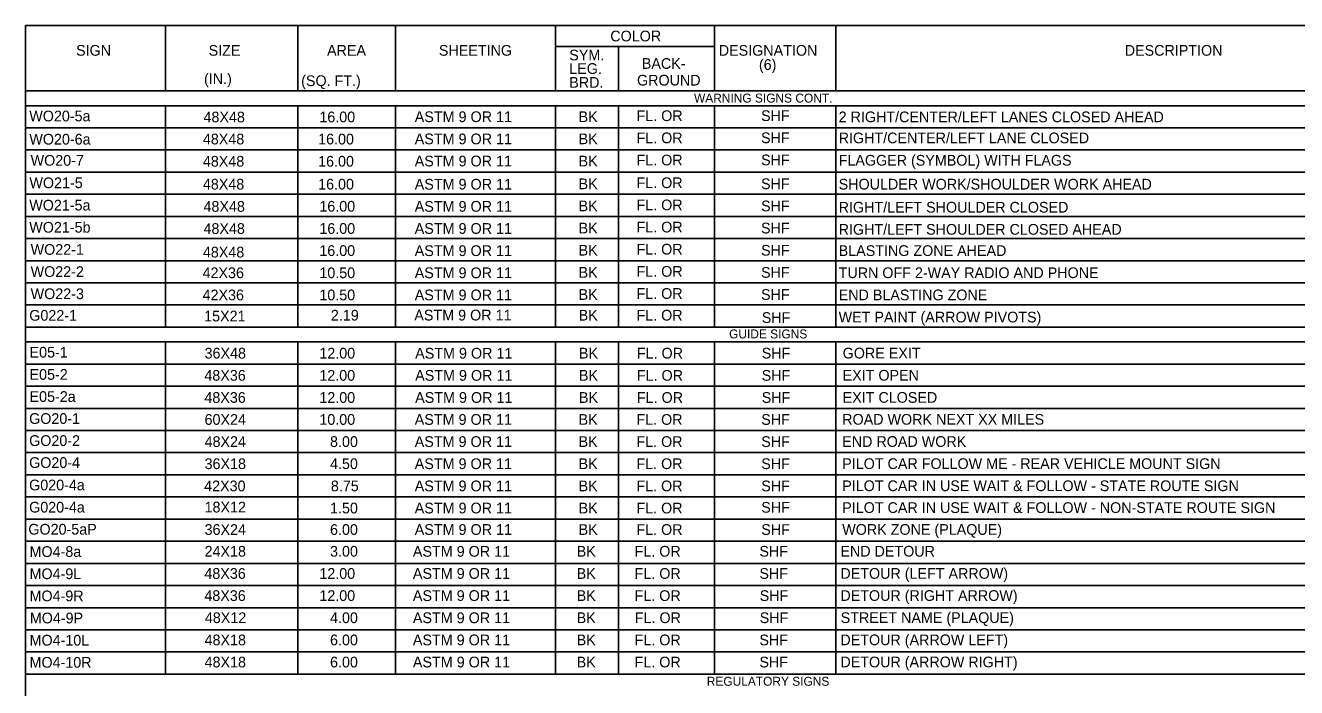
# Model space of a CAD drawing. Extents: x -439.1 to -407.9, y -458.1 to -437.7.
# Drawn here: x -439.11 to -421.29, y -446.95 to -437.68 of the extents above; entities that cross this region are included whole.
import ezdxf

# ---------------------------------------------------------------- set-up
doc = ezdxf.new("R2010")
doc.units = 0
for name, color, linetype in [('Common-Notes', 7, 'Continuous'), ('Level 4', 7, 'Continuous'), ('Level 45', 7, 'Continuous')]:
    doc.layers.add(name, color=color, linetype=linetype)

msp = doc.modelspace()

# ---------------------------------------------------------------- linework, layer by layer
at = {"layer": 'Common-Notes'}
msp.add_line((-439.109, -445.834), (-418.049, -445.834), dxfattribs=at)
at = {"layer": 'Level 4'}
for p, q in [((-439.109, -437.676), (-418.049, -437.676)), ((-439.109, -437.676), (-439.109, -457.952)), ((-437.145, -437.676), (-437.145, -438.59)), ((-435.291, -437.676), (-435.291, -438.59)), ((-433.919, -437.676), (-433.919, -438.59)), ((-431.677, -437.676), (-431.677, -438.59)), ((-429.447, -437.676), (-429.447, -438.59)), ((-427.749, -437.676), (-427.749, -438.59)), ((-431.677, -437.972), (-429.447, -437.972)), ((-430.792, -437.972), (-430.792, -438.59)), ((-439.109, -438.59), (-418.049, -438.59)), ((-439.109, -438.8), (-418.049, -438.8)), ((-437.145, -438.8), (-437.145, -441.903)), ((-435.291, -438.8), (-435.291, -441.903)), ((-433.919, -438.8), (-433.919, -441.903)), ((-431.677, -438.8), (-431.677, -441.903)), ((-430.792, -438.8), (-430.792, -441.903)), ((-429.447, -438.8), (-429.447, -441.903)), ((-427.749, -438.8), (-427.749, -441.903)), ((-439.109, -439.11), (-418.049, -439.11)), ((-439.109, -439.421), (-418.049, -439.421)), ((-439.109, -439.731), (-418.049, -439.731)), ((-439.109, -440.041), (-418.049, -440.041)), ((-439.109, -440.351), (-418.049, -440.351)), ((-439.109, -440.662), (-418.049, -440.662)), ((-439.109, -440.972), (-418.049, -440.972)), ((-439.109, -441.282), (-418.049, -441.282)), ((-439.109, -441.593), (-418.049, -441.593)), ((-439.109, -441.903), (-418.049, -441.903)), ((-439.109, -442.11), (-418.049, -442.11)), ((-437.145, -442.11), (-437.145, -446.765)), ((-435.291, -442.11), (-435.291, -446.455)), ((-433.919, -442.11), (-433.919, -446.765)), ((-431.677, -442.11), (-431.677, -446.455)), ((-430.792, -442.11), (-430.792, -446.455)), ((-429.916, -442.11), (-430.371, -442.11)), ((-429.447, -442.11), (-429.447, -446.765)), ((-427.749, -442.11), (-427.749, -446.765)), ((-439.109, -442.421), (-418.049, -442.421)), ((-439.109, -442.421), (-439.109, -442.731)), ((-439.109, -442.731), (-418.049, -442.731)), ((-439.109, -443.041), (-418.049, -443.041)), ((-439.109, -443.352), (-418.049, -443.352)), ((-439.109, -443.662), (-418.049, -443.662)), ((-439.109, -443.972), (-418.049, -443.972)), ((-439.109, -444.283), (-418.049, -444.283)), ((-439.109, -444.593), (-418.049, -444.593)), ((-439.109, -444.903), (-418.049, -444.903)), ((-439.109, -445.214), (-418.049, -445.214)), ((-439.109, -445.524), (-418.049, -445.524)), ((-439.109, -446.145), (-418.049, -446.145)), ((-439.109, -446.455), (-418.049, -446.455)), ((-435.291, -446.455), (-435.291, -446.765)), ((-431.677, -446.455), (-431.677, -446.765)), ((-430.792, -446.455), (-430.792, -446.765)), ((-418.049, -446.765), (-439.109, -446.765))]:
    msp.add_line(p, q, dxfattribs=at)

# ---------------------------------------------------------------- texts
for s, height, p in [('COLOR', 0.15, (-430.909, -437.899)), ('SIGN', 0.15, (-438.399, -438.1)), ('SIZE', 0.15, (-436.54, -438.1)), ('AREA', 0.15, (-434.88, -438.1)), ('SHEETING', 0.15, (-433.312, -438.1)), ('SYM.', 0.15, (-431.484, -438.165)), ('DESIGNATION', 0.15, (-429.388, -438.1)), ('DESCRIPTION', 0.15, (-423.696, -438.1)), ('LEG.', 0.15, (-431.484, -438.355)), ('BACK-', 0.15, (-430.467, -438.284)), ('(6)', 0.15, (-428.825, -438.299)), ('BRD.', 0.15, (-431.484, -438.549)), ('GROUND', 0.15, (-430.534, -438.518)), ('WARNING SIGNS CONT.', 0.125, (-429.735, -438.756)), ('WO20-5a', 0.15, (-439.055, -439.02)), ('ASTM 9 OR 11', 0.15044, (-433.651, -439.03)), ('BK', 0.15, (-431.353, -439.03)), ('FL. OR', 0.15, (-430.541, -439.016)), ('SHF', 0.15, (-428.795, -439.015)), ('2 RIGHT/CENTER/LEFT LANES CLOSED AHEAD', 0.15, (-427.707, -439.032)), ('WO20-6a', 0.15, (-439.054, -439.345)), ('ASTM 9 OR 11', 0.15044, (-433.651, -439.341)), ('BK', 0.15, (-431.353, -439.34)), ('FL. OR', 0.15, (-430.541, -439.326)), ('SHF', 0.15, (-428.795, -439.325)), ('RIGHT/CENTER/LEFT LANE CLOSED ', 0.15, (-427.707, -439.327)), ('WO20-7', 0.15, (-439.036, -439.641)), ('FL. OR', 0.15, (-430.541, -439.637)), ('SHF', 0.15, (-428.795, -439.635)), ('FLAGGER (SYMBOL) WITH FLAGS', 0.15, (-427.707, -439.64)), ('ASTM 9 OR 11', 0.15044, (-433.651, -439.651)), ('BK', 0.15, (-431.353, -439.651)), ('WO21-5', 0.15, (-439.053, -439.956)), ('ASTM 9 OR 11', 0.15044, (-433.651, -439.976)), ('BK', 0.15, (-431.353, -439.97)), ('FL. OR', 0.15, (-430.541, -439.955)), ('SHF', 0.15, (-428.795, -439.97)), ('SHOULDER WORK/SHOULDER WORK AHEAD', 0.15, (-427.707, -439.975)), ('WO21-5a', 0.15, (-439.055, -440.269)), ('ASTM 9 OR 11', 0.15044, (-433.651, -440.286)), ('BK', 0.15, (-431.353, -440.28)), ('FL. OR', 0.15, (-430.541, -440.266)), ('SHF', 0.15, (-428.795, -440.28)), ('RIGHT/LEFT SHOULDER CLOSED', 0.15, (-427.707, -440.298)), ('WO21-5b', 0.15, (-439.055, -440.579)), ('ASTM 9 OR 11', 0.15044, (-433.651, -440.596)), ('BK', 0.15, (-431.353, -440.59)), ('FL. OR', 0.15, (-430.541, -440.576)), ('SHF', 0.15, (-428.795, -440.59)), ('RIGHT/LEFT SHOULDER CLOSED AHEAD', 0.15, (-427.707, -440.608)), ('WO22-1', 0.15, (-439.036, -440.89)), ('FL. OR', 0.15, (-430.541, -440.886)), ('ASTM 9 OR 11', 0.15044, (-433.651, -440.907)), ('BK', 0.15, (-431.353, -440.9)), ('SHF', 0.15, (-428.795, -440.901)), ('BLASTING ZONE AHEAD', 0.15, (-427.707, -440.906)), ('WO22-2', 0.15, (-439.036, -441.2)), ('ASTM 9 OR 11', 0.15044, (-433.651, -441.217)), ('BK', 0.15, (-431.353, -441.211)), ('FL. OR', 0.15, (-430.541, -441.197)), ('SHF', 0.15, (-428.795, -441.211)), ('TURN OFF 2-WAY RADIO AND PHONE', 0.15, (-427.707, -441.216)), ('WO22-3', 0.15, (-439.036, -441.511)), ('ASTM 9 OR 11', 0.15044, (-433.651, -441.527)), ('BK', 0.15, (-431.353, -441.521)), ('FL. OR', 0.15, (-430.541, -441.507)), ('SHF', 0.15, (-428.795, -441.521)), ('END BLASTING ZONE', 0.15, (-427.707, -441.527)), ('G022-1', 0.15, (-439.055, -441.813)), ('ASTM 9 OR 11', 0.15044, (-433.657, -441.81)), ('BK', 0.15, (-431.352, -441.811)), ('FL. OR', 0.15, (-430.541, -441.811)), ('SHF', 0.15, (-428.785, -441.844)), ('WET PAINT (ARROW PIVOTS)', 0.15, (-427.707, -441.837)), ('GUIDE SIGNS', 0.125, (-429.243, -442.061)), ('E05-1', 0.15, (-439.051, -442.33)), ('ASTM 9 OR 11', 0.15044, (-433.645, -442.344)), ('BK', 0.15, (-431.348, -442.343)), ('FL. OR', 0.15, (-430.536, -442.343)), ('SHF', 0.15, (-428.786, -442.343)), ('GORE EXIT', 0.15, (-427.651, -442.342)), ('E05-2', 0.15, (-439.051, -442.641)), ('ASTM 9 OR 11', 0.15044, (-433.645, -442.654)), ('BK', 0.15, (-431.348, -442.654)), ('FL. OR', 0.15, (-430.536, -442.654)), ('SHF', 0.15, (-428.786, -442.654)), ('EXIT OPEN', 0.15, (-427.651, -442.653)), ('E05-2a', 0.15, (-439.051, -442.951)), ('ASTM 9 OR 11', 0.15044, (-433.645, -442.964)), ('BK', 0.15, (-431.348, -442.964)), ('FL. OR', 0.15, (-430.536, -442.964)), ('SHF', 0.15, (-428.786, -442.964)), ('EXIT CLOSED', 0.15, (-427.651, -442.963)), ('GO20-1', 0.15, (-439.057, -443.259)), ('ASTM 9 OR 11', 0.15044, (-433.651, -443.272)), ('BK', 0.15, (-431.353, -443.272)), ('FL. OR', 0.15, (-430.542, -443.272)), ('SHF', 0.15, (-428.792, -443.272)), ('ROAD WORK NEXT XX MILES', 0.15, (-427.657, -443.27)), ('GO20-2', 0.15, (-439.057, -443.568)), ('ASTM 9 OR 11', 0.15044, (-433.651, -443.582)), ('BK', 0.15, (-431.353, -443.582)), ('FL. OR', 0.15, (-430.542, -443.582)), ('SHF', 0.15, (-428.792, -443.582)), ('END ROAD WORK', 0.15, (-427.657, -443.581)), ('GO20-4', 0.15, (-439.057, -443.876)), ('ASTM 9 OR 11', 0.15044, (-433.651, -443.892)), ('BK', 0.15, (-431.353, -443.892)), ('FL. OR', 0.15, (-430.542, -443.892)), ('SHF', 0.15, (-428.792, -443.892)), ('PILOT CAR FOLLOW ME - REAR VEHICLE MOUNT SIGN', 0.15, (-427.657, -443.891)), ('G020-4a', 0.15, (-439.057, -444.19)), ('ASTM 9 OR 11', 0.15044, (-433.651, -444.203)), ('BK', 0.15, (-431.353, -444.203)), ('FL. OR', 0.15, (-430.542, -444.203)), ('SHF', 0.15, (-428.792, -444.203)), ('PILOT CAR IN USE WAIT & FOLLOW - STATE ROUTE SIGN', 0.15, (-427.657, -444.201)), ('G020-4a', 0.15, (-439.057, -444.501)), ('ASTM 9 OR 11', 0.15044, (-433.651, -444.513)), ('BK', 0.15, (-431.353, -444.513)), ('FL. OR', 0.15, (-430.542, -444.513)), ('SHF', 0.15, (-428.792, -444.503)), ('PILOT CAR IN USE WAIT & FOLLOW - NON-STATE ROUTE SIGN', 0.15, (-427.657, -444.507)), ('GO20-5aP', 0.15, (-439.068, -444.81)), ('ASTM 9 OR 11', 0.15044, (-433.651, -444.814)), ('FL. OR', 0.15, (-430.542, -444.814)), ('SHF', 0.15, (-428.792, -444.814)), ('WORK ZONE (PLAQUE)', 0.15, (-427.657, -444.813)), ('BK', 0.15, (-431.353, -444.814)), ('MO4-8a', 0.15, (-439.051, -445.123)), ('ASTM 9 OR 11', 0.15044, (-433.677, -445.12)), ('BK', 0.15, (-431.38, -445.119)), ('FL. OR', 0.15, (-430.568, -445.119)), ('SHF', 0.15, (-428.818, -445.119)), ('END DETOUR', 0.15, (-427.683, -445.118)), ('MO4-9L', 0.15, (-439.051, -445.434)), ('ASTM 9 OR 11', 0.15044, (-433.677, -445.43)), ('BK', 0.15, (-431.38, -445.43)), ('FL. OR', 0.15, (-430.568, -445.43)), ('SHF', 0.15, (-428.818, -445.43)), ('DETOUR (LEFT ARROW)', 0.15, (-427.683, -445.429)), ('MO4-9R', 0.15, (-439.051, -445.744)), ('ASTM 9 OR 11', 0.15044, (-433.677, -445.74)), ('BK', 0.15, (-431.38, -445.74)), ('FL. OR', 0.15, (-430.568, -445.74)), ('SHF', 0.15, (-428.814, -445.74)), ('DETOUR (RIGHT ARROW)', 0.15, (-427.683, -445.739)), ('MO4-9P', 0.15, (-439.047, -446.054)), ('ASTM 9 OR 11', 0.15044, (-433.677, -446.051)), ('BK', 0.15, (-431.38, -446.05)), ('FL. OR', 0.15, (-430.565, -446.05)), ('SHF', 0.15, (-428.814, -446.05)), ('STREET NAME (PLAQUE)', 0.15, (-427.679, -446.049)), ('MO4-10L', 0.15, (-439.051, -446.365)), ('ASTM 9 OR 11', 0.15044, (-433.677, -446.361)), ('BK', 0.15, (-431.38, -446.361)), ('FL. OR', 0.15, (-430.568, -446.361)), ('SHF', 0.15, (-428.818, -446.361)), ('DETOUR (ARROW LEFT)', 0.15, (-427.683, -446.36)), ('MO4-10R', 0.15, (-439.051, -446.675)), ('ASTM 9 OR 11', 0.15044, (-433.677, -446.671)), ('BK', 0.15, (-431.38, -446.671)), ('FL. OR', 0.15, (-430.568, -446.671)), ('SHF', 0.15, (-428.818, -446.671)), ('DETOUR (ARROW RIGHT)', 0.15, (-427.683, -446.67)), ('REGULATORY SIGNS', 0.125, (-429.556, -446.928))]:
    msp.add_text(s, height=height, dxfattribs=at).set_placement(p)
at = {"layer": 'Level 45'}
for s, p in [('(IN.)', (-436.605, -438.498)), ('(SQ. FT.)', (-435.243, -438.525)), ('48X48', (-436.612, -439.034)), ('16.00', (-434.988, -439.033)), ('48X48', (-436.621, -439.343)), ('16.00', (-435.005, -439.343)), ('48X48', (-436.621, -439.654)), ('16.00', (-435.005, -439.654)), ('48X48', (-436.621, -439.975)), ('16.00', (-435.005, -439.975)), ('48X48', (-436.612, -440.287)), ('16.00', (-434.988, -440.285)), ('48X48', (-436.612, -440.597)), ('16.00', (-434.988, -440.596)), ('48X48', (-436.621, -440.927)), ('16.00', (-434.988, -440.906)), ('42X36', (-436.625, -441.217)), ('10.50', (-434.988, -441.217)), ('42X36', (-436.625, -441.527)), ('10.50', (-434.988, -441.527)), ('15X21', (-436.603, -441.823)), ('2.19', (-434.826, -441.811)), ('36X48', (-436.597, -442.343)), ('12.00', (-434.988, -442.343)), ('48X36', (-436.6, -442.654)), ('12.00', (-434.988, -442.654)), ('48X36', (-436.6, -442.964)), ('12.00', (-434.988, -442.964)), ('60X24', (-436.597, -443.272)), ('10.00', (-434.988, -443.272)), ('48X24', (-436.597, -443.582)), ('8.00', (-434.838, -443.582)), ('36X18', (-436.597, -443.892)), ('4.50', (-434.838, -443.892)), ('42X30', (-436.603, -444.203)), ('8.75', (-434.826, -444.203)), ('18X12', (-436.597, -444.5)), ('1.50', (-434.838, -444.513)), ('36X24', (-436.597, -444.814)), ('6.00', (-434.838, -444.814)), ('24X18', (-436.597, -445.119)), ('3.00', (-434.838, -445.119)), ('48X36', (-436.6, -445.43)), ('12.00', (-434.988, -445.43)), ('48X36', (-436.6, -445.74)), ('12.00', (-434.988, -445.74)), ('48X12', (-436.593, -446.05)), ('4.00', (-434.838, -446.05)), ('48X18', (-436.597, -446.361)), ('6.00', (-434.838, -446.361)), ('48X18', (-436.597, -446.671)), ('6.00', (-434.838, -446.671))]:
    msp.add_text(s, height=0.15, dxfattribs=at).set_placement(p)

doc.saveas('drawing.dxf')
